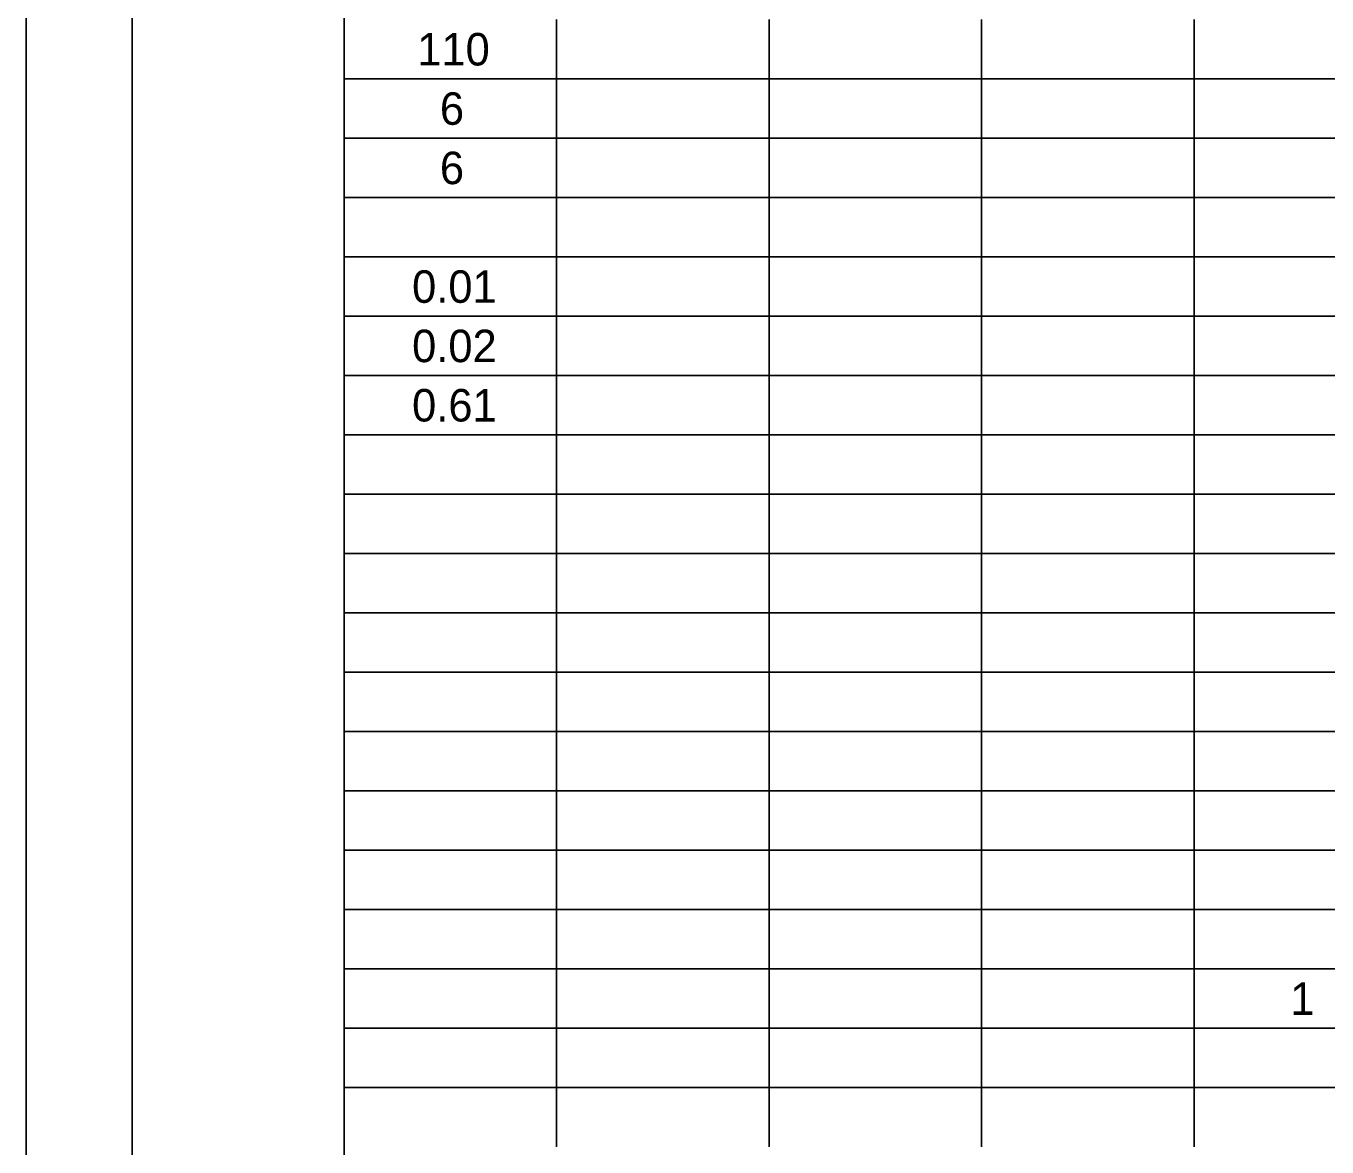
# Model space of a CAD drawing. Extents: x 0 to 34, y 0 to 22.
# Drawn here: x 0 to 6.14, y 11.42 to 16.71 of the extents above; entities that cross this region are included whole.
import ezdxf

# ---------------------------------------------------------------- set-up
doc = ezdxf.new("R2010")
doc.units = 0
for name, color, linetype in [('Default', 7, 'Continuous'), ('SH_Border', 7, 'Continuous'), ('SH_Cut_Line', 7, 'Continuous')]:
    doc.layers.add(name, color=color, linetype=linetype)

msp = doc.modelspace()

# ---------------------------------------------------------------- linework, layer by layer
at = {"layer": 'Default'}
for p, q in [((1.5, 16.74), (1.5, 16.18)), ((2.5025, 16.74), (2.5025, 16.18)), ((3.5051, 16.74), (3.5051, 16.18)), ((4.5076, 16.74), (4.5076, 16.18)), ((5.5101, 16.74), (5.5101, 16.18)), ((1.5, 16.46), (6.5126, 16.46)), ((1.5, 16.18), (6.5126, 16.18)), ((1.5, 16.18), (1.5, 15.9)), ((2.5025, 16.18), (2.5025, 15.9)), ((3.5051, 16.18), (3.5051, 15.9)), ((4.5076, 16.18), (4.5076, 15.9)), ((5.5101, 16.18), (5.5101, 15.9)), ((1.5, 15.9), (6.5126, 15.9)), ((1.5, 15.9), (1.5, 15.62)), ((2.5025, 15.9), (2.5025, 15.62)), ((3.5051, 15.9), (3.5051, 15.62)), ((4.5076, 15.9), (4.5076, 15.62)), ((5.5101, 15.9), (5.5101, 15.62)), ((1.5, 15.62), (6.5126, 15.62)), ((1.5, 15.62), (1.5, 15.34)), ((2.5025, 15.62), (2.5025, 15.34)), ((3.5051, 15.62), (3.5051, 15.34)), ((4.5076, 15.62), (4.5076, 15.34)), ((5.5101, 15.62), (5.5101, 15.34)), ((1.5, 15.34), (6.5126, 15.34)), ((1.5, 15.34), (1.5, 14.78)), ((2.5025, 15.34), (2.5025, 14.78)), ((3.5051, 15.34), (3.5051, 14.78)), ((4.5076, 15.34), (4.5076, 14.78)), ((5.5101, 15.34), (5.5101, 14.78)), ((1.5, 15.06), (6.5126, 15.06)), ((1.5, 14.78), (6.5126, 14.78)), ((1.5, 14.78), (1.5, 14.5)), ((2.5025, 14.78), (2.5025, 14.5)), ((3.5051, 14.78), (3.5051, 14.5)), ((4.5076, 14.78), (4.5076, 14.5)), ((5.5101, 14.78), (5.5101, 14.5)), ((1.5, 14.5), (6.5126, 14.5)), ((1.5, 14.5), (1.5, 14.22)), ((2.5025, 14.5), (2.5025, 14.22)), ((3.5051, 14.5), (3.5051, 14.22)), ((4.5076, 14.5), (4.5076, 14.22)), ((5.5101, 14.5), (5.5101, 14.22)), ((1.5, 14.22), (6.5126, 14.22)), ((1.5, 14.22), (1.5, 13.94)), ((2.5025, 14.22), (2.5025, 13.94)), ((3.5051, 14.22), (3.5051, 13.94)), ((4.5076, 14.22), (4.5076, 13.94)), ((5.5101, 14.22), (5.5101, 13.94)), ((1.5, 13.94), (6.5126, 13.94)), ((1.5, 13.94), (1.5, 11.7)), ((2.5025, 13.94), (2.5025, 11.7)), ((3.5051, 13.94), (3.5051, 11.7)), ((4.5076, 13.94), (4.5076, 11.7)), ((5.5101, 13.94), (5.5101, 11.7)), ((1.5, 13.66), (6.5126, 13.66)), ((1.5, 13.38), (6.5126, 13.38)), ((1.5, 13.1), (6.5126, 13.1)), ((1.5, 12.82), (6.5126, 12.82)), ((1.5, 12.54), (6.5126, 12.54)), ((1.5, 12.26), (6.5126, 12.26)), ((1.5, 11.98), (6.5126, 11.98)), ((1.5, 11.7), (6.5126, 11.7)), ((1.5, 11.7), (1.5, 11.42)), ((2.5025, 11.7), (2.5025, 11.42)), ((3.5051, 11.7), (3.5051, 11.42)), ((4.5076, 11.7), (4.5076, 11.42)), ((5.5101, 11.7), (5.5101, 11.42))]:
    msp.add_line(p, q, dxfattribs=at)
at = {"layer": 'SH_Border'}
for points in [[(0.5, 21.5), (1.5, 21.5), (1.5, 0.5), (0.5, 0.5)], [(1.5, 21.5), (33.5, 21.5), (33.5, 0.5), (1.5, 0.5)]]:
    msp.add_lwpolyline(points, close=True, dxfattribs=at)
at = {"layer": 'SH_Cut_Line'}
msp.add_lwpolyline([(0, 0), (34, 0), (34, 22), (0, 22)], close=True, dxfattribs=at)

# ---------------------------------------------------------------- texts
at = {"layer": 'Default'}
for s, height, p in [('110', 0.15333, (1.8456, 16.5233)), ('6', 0.1533, (1.9523, 16.2433)), ('6', 0.1533, (1.9523, 15.9633)), ('0.01', 0.15333, (1.8212, 15.4033)), ('0.02', 0.15333, (1.8213, 15.1233)), ('0.61', 0.15333, (1.8212, 14.8433)), ('1', 0.1533, (5.964, 12.0433))]:
    msp.add_text(s, height=height, dxfattribs=at).set_placement(p)

doc.saveas('drawing.dxf')
